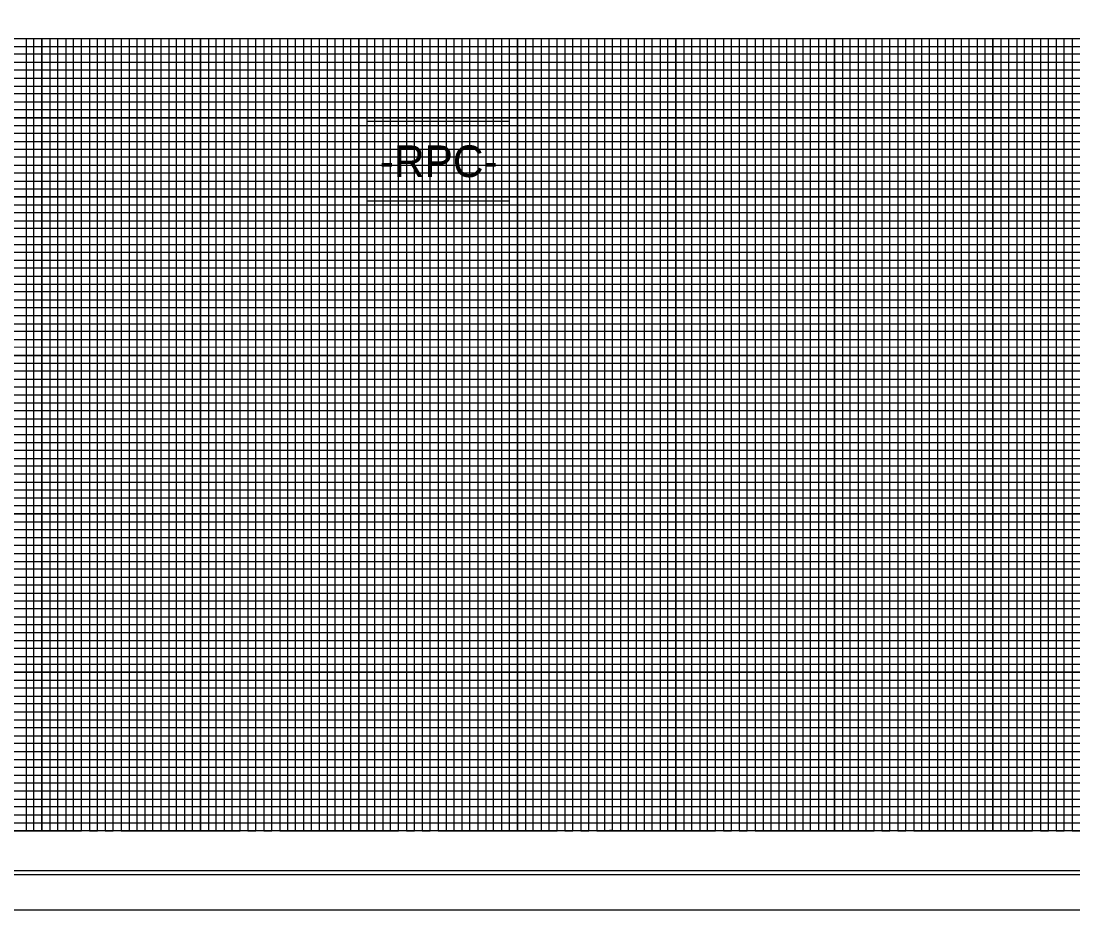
# Model space of a CAD drawing. Extents: x 1648862 to 1650855, y 808691 to 809791.
# Drawn here: x 1649516 to 1650180, y 808691 to 809252 of the extents above; entities that cross this region are included whole.
import ezdxf

# ---------------------------------------------------------------- set-up
doc = ezdxf.new("R2010")
doc.units = 0
for name, color, linetype in [('Exist Vertical Profile Horizontal Axis Label Major', 7, 'Continuous'), ('Prop Grid Mask', 7, 'Continuous'), ('Sheet Cutting Line CELL', 7, 'Continuous'), ('Sheet DOT Grid CELL', 7, 'Continuous'), ('Sheet Layout Profile Border Port 2', 7, 'Continuous'), ('Sheet Plot Border Inside CELL', 7, 'Continuous'), ('Sheet Plot Border Outside CELL', 7, 'Continuous'), ('Sheet Profile CELL', 7, 'Continuous'), ('Sheet Profile Grid Major CELL', 7, 'Continuous'), ('Sheet Profile Grid Middle CELL', 7, 'Continuous'), ('Sheet Profile Grid Minor CELL', 7, 'Continuous')]:
    doc.layers.add(name, color=color, linetype=linetype)

msp = doc.modelspace()

# ---------------------------------------------------------------- linework, layer by layer
at = {"layer": 'Prop Grid Mask'}
msp.add_lwpolyline([(1649734.28, 809188.52), (1649734.28, 809138.52), (1649824.28, 809138.52), (1649824.28, 809188.52)], close=True, dxfattribs=at)
at = {"layer": 'Sheet Cutting Line CELL'}
msp.add_line((1648862.28, 808691.02), (1650546.28, 808691.02), dxfattribs=at)
at = {"layer": 'Sheet DOT Grid CELL'}
for p, q in [((1649029.28, 809241.02), (1650529.17, 809241.02)), ((1649529.28, 809241.02), (1649529.28, 808741.02)), ((1649579.28, 809241.02), (1649579.28, 808741.02)), ((1649629.28, 809241.02), (1649629.28, 808741.02)), ((1649679.28, 809241.02), (1649679.28, 808741.02)), ((1649729.28, 809241.02), (1649729.28, 808741.02)), ((1649779.28, 809241.02), (1649779.28, 808741.02)), ((1649829.28, 809241.02), (1649829.28, 808741.02)), ((1649879.28, 809241.02), (1649879.28, 808741.02)), ((1649929.28, 809241.02), (1649929.28, 808741.02)), ((1649979.28, 809241.02), (1649979.28, 808741.02)), ((1650029.28, 809241.02), (1650029.28, 808741.02)), ((1650079.28, 809241.02), (1650079.28, 808741.02)), ((1650129.28, 809241.02), (1650129.28, 808741.02)), ((1650179.28, 809241.02), (1650179.28, 808741.02)), ((1649029.28, 809191.02), (1650529.17, 809191.02)), ((1649029.28, 809141.02), (1650529.17, 809141.02)), ((1649029.28, 809091.02), (1650529.17, 809091.02)), ((1649029.28, 809041.02), (1650529.17, 809041.02)), ((1649029.28, 808991.02), (1650529.17, 808991.02)), ((1649029.28, 808941.02), (1650529.17, 808941.02)), ((1649029.28, 808891.02), (1650529.17, 808891.02)), ((1649029.28, 808841.02), (1650529.17, 808841.02)), ((1649029.28, 808791.02), (1650529.17, 808791.02))]:
    msp.add_line(p, q, dxfattribs=at)
at = {"layer": 'Sheet Layout Profile Border Port 2'}
msp.add_lwpolyline([(1649079.28, 809241.02), (1650479.28, 809241.02), (1650479.28, 808741.02), (1649079.28, 808741.02)], close=True, dxfattribs=at)
at = {"layer": 'Sheet Plot Border Inside CELL'}
msp.add_lwpolyline([(1648875.28, 808713.47), (1650541.78, 808713.47), (1650541.78, 809768.57), (1648875.28, 809768.57)], close=True, dxfattribs=at)
at = {"layer": 'Sheet Plot Border Outside CELL'}
msp.add_lwpolyline([(1648862.28, 808691.02), (1650546.28, 808691.02), (1650546.28, 809791.02), (1648862.28, 809791.02)], close=True, dxfattribs=at)
at = {"layer": 'Sheet Profile CELL'}
for p, q in [((1649029.28, 809241.02), (1650529.28, 809241.02)), ((1650529.28, 808741.02), (1649029.28, 808741.02)), ((1649029.28, 808716.02), (1650529.28, 808716.02))]:
    msp.add_line(p, q, dxfattribs=at)
msp.add_lwpolyline([(1650529.28, 809766.02), (1649029.28, 809766.02), (1649029.28, 808716.02), (1650529.28, 808716.02)], close=True, dxfattribs=at)
at = {"layer": 'Sheet Profile Grid Major CELL'}
for p, q in [((1649529.28, 809241.02), (1649579.28, 809241.02)), ((1649629.28, 809241.02), (1649679.28, 809241.02)), ((1649729.28, 809241.02), (1649779.28, 809241.02)), ((1649829.28, 809241.02), (1649879.28, 809241.02)), ((1649929.28, 809241.02), (1649979.28, 809241.02)), ((1650029.28, 809241.02), (1650079.28, 809241.02)), ((1650129.28, 809241.02), (1650179.28, 809241.02))]:
    msp.add_line(p, q, dxfattribs=at)
for points in [[(1649479.28, 808741.02), (1649529.28, 808741.02), (1649529.28, 809241.02), (1649579.28, 809241.02), (1649579.28, 808741.02), (1649629.28, 808741.02), (1649629.28, 809241.02), (1649679.28, 809241.02), (1649679.28, 808741.02), (1649729.28, 808741.02), (1649729.28, 809241.02), (1649779.28, 809241.02), (1649779.28, 808741.02), (1649829.28, 808741.02), (1649829.28, 809241.02), (1649879.28, 809241.02), (1649879.28, 808741.02), (1649929.28, 808741.02), (1649929.28, 809241.02), (1649979.28, 809241.02), (1649979.28, 808741.02), (1650029.28, 808741.02), (1650029.28, 809241.02), (1650079.28, 809241.02), (1650079.28, 808741.02), (1650129.28, 808741.02), (1650129.28, 809241.02), (1650179.28, 809241.02), (1650179.28, 808741.02), (1650229.28, 808741.02)], [(1650529.28, 809191.02), (1649029.28, 809191.02)], [(1650529.28, 809141.02), (1649029.28, 809141.02), (1649029.28, 809091.02), (1650529.28, 809091.02)], [(1650529.28, 809041.02), (1649029.28, 809041.02), (1649029.28, 808991.02), (1650529.28, 808991.02)], [(1650529.28, 808941.02), (1649029.28, 808941.02), (1649029.28, 808891.02), (1650529.28, 808891.02)], [(1650529.28, 808841.02), (1649029.28, 808841.02), (1649029.28, 808841.02), (1649029.28, 808791.02), (1650529.28, 808791.02)], [(1650529.28, 808741.02), (1649029.28, 808741.02)]]:
    msp.add_lwpolyline(points, dxfattribs=at)
at = {"layer": 'Sheet Profile Grid Middle CELL'}
for points in [[(1649504.28, 808741.02), (1649554.28, 808741.02), (1649554.28, 809241.02), (1649604.28, 809241.02), (1649604.28, 808741.02), (1649654.28, 808741.02), (1649654.28, 808741.02), (1649654.28, 809241.02), (1649704.28, 809241.02), (1649704.28, 808741.02), (1649754.28, 808741.02), (1649754.28, 809241.02), (1649804.28, 809241.02), (1649804.28, 808741.02), (1649854.28, 808741.02), (1649854.28, 809241.02), (1649904.28, 809241.02), (1649904.28, 808741.02), (1649954.28, 808741.02), (1649954.28, 809241.02), (1650004.28, 809241.02), (1650004.28, 808741.02), (1650054.28, 808741.02), (1650054.28, 809241.02), (1650104.28, 809241.02), (1650104.28, 808741.02), (1650154.28, 808741.02), (1650154.28, 809241.02), (1650204.28, 809241.02)], [(1649029.28, 809216.02), (1650529.28, 809216.02)], [(1650529.28, 809166.02), (1649029.28, 809166.02), (1649029.28, 809116.02), (1650529.28, 809116.02)], [(1650529.28, 809066.02), (1649029.28, 809066.02), (1649029.28, 809016.02), (1650529.28, 809016.02)], [(1650529.28, 808966.02), (1649029.28, 808966.02), (1649029.28, 808916.02), (1650529.28, 808916.02)], [(1650529.28, 808866.02), (1649029.28, 808866.02), (1649029.28, 808816.02), (1650529.28, 808816.02)], [(1650529.28, 808766.02), (1649029.28, 808766.02)]]:
    msp.add_lwpolyline(points, dxfattribs=at)
at = {"layer": 'Sheet Profile Grid Minor CELL'}
for p, q in [((1649079.28, 809236.02), (1650479.28, 809236.02)), ((1650479.28, 809231.02), (1649079.28, 809231.02)), ((1649079.28, 809226.02), (1650479.28, 809226.02)), ((1650479.28, 809221.02), (1649079.28, 809221.02)), ((1649079.28, 809211.02), (1650479.28, 809211.02)), ((1650479.28, 809206.02), (1649079.28, 809206.02)), ((1649079.28, 809201.02), (1650479.28, 809201.02)), ((1650479.28, 809196.02), (1649079.28, 809196.02)), ((1649079.28, 809186.02), (1650479.28, 809186.02)), ((1650479.28, 809181.02), (1649079.28, 809181.02)), ((1649079.28, 809176.02), (1650479.28, 809176.02)), ((1650479.28, 809171.02), (1649079.28, 809171.02)), ((1649079.28, 809161.02), (1650479.28, 809161.02)), ((1650479.28, 809156.02), (1649079.28, 809156.02)), ((1649079.28, 809151.02), (1650479.28, 809151.02)), ((1650479.28, 809146.02), (1649079.28, 809146.02)), ((1649079.28, 809136.02), (1650479.28, 809136.02)), ((1650479.28, 809131.02), (1649079.28, 809131.02)), ((1649079.28, 809126.02), (1650479.28, 809126.02)), ((1650479.28, 809121.02), (1649079.28, 809121.02)), ((1649079.28, 809111.02), (1650479.28, 809111.02)), ((1650479.28, 809106.02), (1649079.28, 809106.02)), ((1649079.28, 809101.02), (1650479.28, 809101.02)), ((1650479.28, 809096.02), (1649079.28, 809096.02)), ((1649079.28, 809086.02), (1650479.28, 809086.02)), ((1650479.28, 809081.02), (1649079.28, 809081.02)), ((1649079.28, 809076.02), (1650479.28, 809076.02)), ((1650479.28, 809071.02), (1649079.28, 809071.02)), ((1649079.28, 809061.02), (1650479.28, 809061.02)), ((1650479.28, 809056.02), (1649079.28, 809056.02)), ((1649079.28, 809051.02), (1650479.28, 809051.02)), ((1650479.28, 809046.02), (1649079.28, 809046.17)), ((1649079.28, 809036.02), (1650479.28, 809036.02)), ((1650479.28, 809031.02), (1649079.28, 809031.02)), ((1649079.28, 809026.02), (1650479.28, 809026.02)), ((1650479.28, 809021.02), (1649079.28, 809021.02)), ((1649079.28, 809011.02), (1650479.28, 809011.02)), ((1650479.28, 809006.02), (1649079.28, 809006.02)), ((1649079.28, 809001.02), (1650479.28, 809001.02)), ((1650479.28, 808996.02), (1649079.28, 808996.02)), ((1649079.28, 808986.02), (1650479.28, 808986.02)), ((1650479.28, 808981.02), (1649079.28, 808981.02)), ((1649079.28, 808976.02), (1650479.28, 808976.02)), ((1650479.28, 808971.02), (1649079.28, 808971.02)), ((1649079.28, 808961.02), (1650479.28, 808961.02)), ((1650479.28, 808956.02), (1649079.28, 808956.02)), ((1649079.28, 808951.02), (1650479.28, 808951.02)), ((1650479.28, 808946.02), (1649079.28, 808946.02)), ((1649079.28, 808936.02), (1650479.28, 808936.02)), ((1650479.28, 808931.02), (1649079.28, 808931.02)), ((1649079.28, 808926.02), (1650479.28, 808926.02)), ((1650479.28, 808921.02), (1649079.28, 808921.02)), ((1649079.28, 808911.02), (1650479.28, 808911.02)), ((1650479.28, 808906.02), (1649079.28, 808906.02)), ((1649079.28, 808901.02), (1650479.28, 808901.02)), ((1650479.28, 808896.02), (1649079.28, 808896.02)), ((1649079.28, 808886.02), (1650479.28, 808886.02)), ((1650479.28, 808881.02), (1649079.28, 808881.02)), ((1649079.28, 808876.02), (1650479.28, 808876.02)), ((1650479.28, 808871.02), (1649079.28, 808871.02)), ((1649079.28, 808861.02), (1650479.28, 808861.02)), ((1650479.28, 808856.02), (1649079.28, 808856.02)), ((1649079.28, 808851.02), (1650479.28, 808851.02)), ((1650479.28, 808846.02), (1649079.28, 808846.02)), ((1649079.28, 808836.02), (1650479.28, 808836.02)), ((1650479.28, 808831.02), (1649079.28, 808831.02)), ((1649079.28, 808826.02), (1650479.28, 808826.02)), ((1650479.28, 808821.02), (1649079.28, 808821.02)), ((1649079.28, 808811.02), (1650479.28, 808811.02)), ((1650479.28, 808806.02), (1649079.28, 808806.02)), ((1649079.28, 808801.02), (1650479.28, 808801.02)), ((1650479.28, 808796.02), (1649079.28, 808796.02)), ((1649079.28, 808786.02), (1650479.28, 808786.02)), ((1650479.28, 808781.02), (1649079.28, 808781.02)), ((1649079.28, 808776.02), (1650479.28, 808776.02)), ((1650479.28, 808771.02), (1649079.28, 808771.02)), ((1649079.28, 808761.02), (1650479.28, 808761.02)), ((1650479.28, 808756.02), (1649079.28, 808756.02)), ((1649079.28, 808751.02), (1650479.28, 808751.02)), ((1649079.28, 808746.02), (1650479.28, 808746.02))]:
    msp.add_line(p, q, dxfattribs=at)
for points in [[(1649514.28, 809241.02), (1649519.28, 809241.02), (1649519.28, 808741.02), (1649524.28, 808741.02), (1649524.28, 809241.02), (1649534.28, 809241.02), (1649534.28, 808741.02), (1649539.28, 808741.02), (1649539.28, 809241.02), (1649544.28, 809241.02), (1649544.28, 808741.02), (1649549.28, 808741.02), (1649549.28, 809241.02), (1649559.28, 809241.02), (1649559.28, 808741.02), (1649564.28, 808741.02), (1649564.28, 809241.02), (1649569.28, 809241.02), (1649569.28, 808741.02), (1649574.28, 808741.02), (1649574.28, 809241.02), (1649584.28, 809241.02), (1649584.28, 808741.02), (1649589.28, 808741.02), (1649589.28, 809241.02), (1649594.28, 809241.02), (1649594.28, 808741.02), (1649599.28, 808741.02), (1649599.28, 809241.02), (1649609.28, 809241.02)], [(1649609.28, 809241.02), (1649609.28, 808741.02), (1649614.28, 808741.02), (1649614.28, 809241.02), (1649619.28, 809241.02), (1649619.28, 808741.02), (1649624.28, 808741.02), (1649624.28, 809241.02), (1649634.28, 809241.02), (1649634.28, 808741.02), (1649639.28, 808741.02), (1649639.28, 809241.02), (1649644.28, 809241.02), (1649644.28, 808741.02), (1649649.28, 808741.02), (1649649.28, 809241.02), (1649659.28, 809241.02), (1649659.28, 808741.02), (1649664.28, 808741.02), (1649664.28, 809241.02), (1649669.28, 809241.02), (1649669.28, 808741.02), (1649674.28, 808741.02), (1649674.28, 809241.02), (1649684.28, 809241.02), (1649684.28, 808741.02), (1649689.28, 808741.02), (1649689.28, 809241.02), (1649694.28, 809241.02), (1649694.28, 808741.02), (1649699.28, 808741.02), (1649699.28, 809241.02), (1649709.28, 809241.02), (1649709.28, 808741.02), (1649714.28, 808741.02), (1649714.28, 809241.02), (1649719.28, 809241.02), (1649719.28, 808741.02), (1649724.28, 808741.02), (1649724.28, 809241.02), (1649734.28, 809241.02), (1649734.28, 808741.02), (1649734.28, 808741.02), (1649739.28, 808741.02), (1649739.28, 809241.02), (1649744.28, 809241.02), (1649744.28, 808741.02), (1649749.28, 808741.02), (1649749.28, 809241.02), (1649759.28, 809241.02), (1649759.28, 808741.02), (1649764.28, 808741.02), (1649764.28, 809241.02), (1649769.28, 809241.02), (1649769.28, 808741.02), (1649774.28, 808741.02), (1649774.28, 809241.02), (1649784.28, 809241.02), (1649784.28, 808741.02), (1649789.28, 808741.02), (1649789.28, 809241.02), (1649794.28, 809241.02), (1649794.28, 808741.02), (1649799.28, 808741.02), (1649799.28, 809241.02), (1649809.28, 809241.02), (1649809.28, 808741.02), (1649814.28, 808741.02), (1649814.28, 809241.02), (1649819.28, 809241.02), (1649819.28, 808741.02), (1649824.28, 808741.02), (1649824.28, 809241.02), (1649834.28, 809241.02), (1649834.28, 808741.02), (1649839.28, 808741.02), (1649839.28, 809241.02), (1649844.28, 809241.02), (1649844.28, 808741.02), (1649849.28, 808741.02), (1649849.28, 809241.02), (1649859.28, 809241.02), (1649859.28, 808741.02), (1649864.28, 808741.02), (1649864.28, 809241.02), (1649869.28, 809241.02), (1649869.28, 808741.02), (1649874.28, 808741.02), (1649874.28, 809241.02), (1649884.28, 809241.02), (1649884.28, 808741.02), (1649888.98, 808741.57), (1649889.28, 808741.02), (1649889.28, 809241.02), (1649894.28, 809241.02), (1649894.28, 808741.02), (1649899.28, 808741.02), (1649899.28, 809241.02), (1649909.28, 809241.02), (1649909.28, 808741.02), (1649914.28, 808741.02)], [(1649914.28, 808741.02), (1649914.28, 809241.02), (1649919.28, 809241.02), (1649919.28, 808741.02), (1649924.28, 808741.02), (1649924.28, 809241.02), (1649934.28, 809241.02), (1649934.28, 808741.02), (1649939.28, 808741.02), (1649939.28, 809241.02), (1649944.28, 809241.02), (1649944.28, 808741.02), (1649949.28, 808741.02), (1649949.28, 809241.02), (1649959.28, 809241.02), (1649959.28, 808741.02), (1649964.28, 808741.02), (1649964.28, 809241.02), (1649969.28, 809241.02), (1649969.28, 808741.02), (1649974.28, 808741.02), (1649974.28, 809241.02), (1649984.28, 809241.02), (1649984.28, 808741.02), (1649989.28, 808741.02), (1649989.28, 809241.02), (1649994.28, 809241.02), (1649994.28, 808741.02), (1649999.28, 808741.02), (1649999.28, 809241.02), (1650009.28, 809241.02), (1650009.28, 808741.02), (1650014.28, 808741.02), (1650014.28, 809241.02), (1650019.28, 809241.02), (1650019.28, 808741.02), (1650024.28, 808741.02), (1650024.28, 809241.02), (1650034.28, 809241.02), (1650034.28, 808741.02), (1650039.28, 808741.02), (1650039.28, 809241.02), (1650044.28, 809241.02), (1650044.28, 808741.02), (1650049.28, 808741.02), (1650049.28, 809241.02), (1650059.28, 809241.02), (1650059.28, 808741.02), (1650064.28, 808741.02), (1650064.28, 809241.02), (1650069.28, 809241.02), (1650069.28, 808741.02), (1650074.28, 808741.02), (1650074.28, 809241.02), (1650084.28, 809241.02), (1650084.28, 808741.02), (1650089.28, 808741.02), (1650089.28, 809241.02), (1650094.28, 809241.02), (1650094.28, 808741.02), (1650099.28, 808741.02), (1650099.28, 809241.02), (1650109.28, 809241.02), (1650109.28, 808741.02), (1650114.28, 808741.02), (1650114.28, 809241.02), (1650119.28, 809241.02), (1650119.28, 808741.02), (1650124.28, 808741.02), (1650124.28, 809241.02), (1650134.28, 809241.02), (1650134.28, 808741.02), (1650139.28, 808741.02), (1650139.28, 809241.02), (1650144.28, 809241.02), (1650144.28, 808741.02), (1650149.28, 808741.02), (1650149.28, 809241.02), (1650159.28, 809241.02), (1650159.28, 808741.02), (1650164.28, 808741.02), (1650164.28, 809241.02), (1650169.28, 809241.02), (1650169.28, 808741.02), (1650174.28, 808741.02), (1650174.28, 809241.02), (1650184.28, 809241.02)]]:
    msp.add_lwpolyline(points, dxfattribs=at)

# ---------------------------------------------------------------- texts
at = {"layer": 'Exist Vertical Profile Horizontal Axis Label Major'}
msp.add_text('-RPC-', height=20, dxfattribs=at).set_placement((1649742.49, 809153.52))

doc.saveas('drawing.dxf')
